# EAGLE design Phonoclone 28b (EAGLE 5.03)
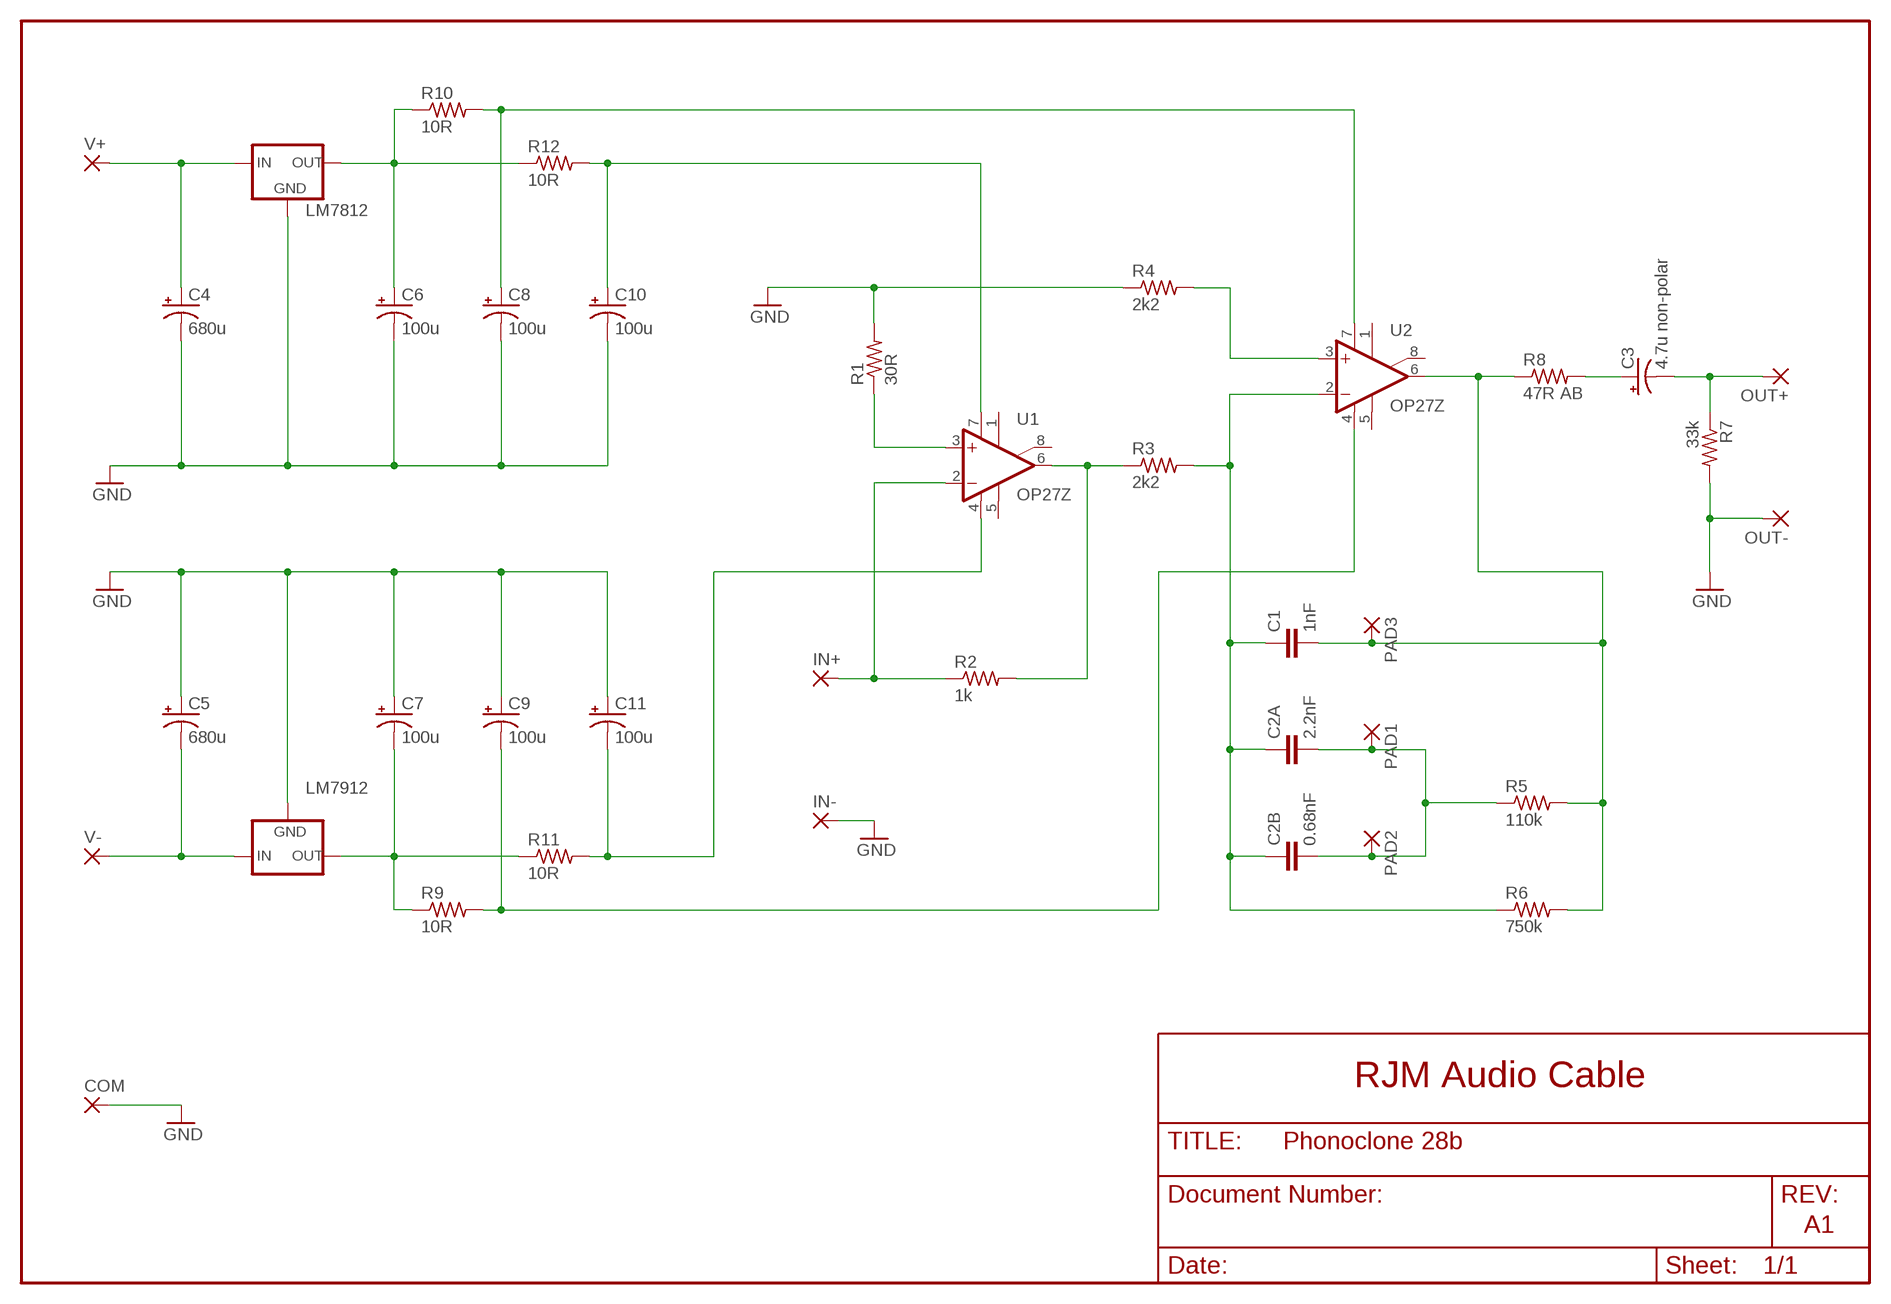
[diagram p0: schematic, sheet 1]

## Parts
C1  1nF  C-EU075-SS  [075-SS]
C2A  2.2nF  C-EU075-SS  [075-SS]
C2B  0.68nF  C-EU075-SS  [075-SS]
C3  4.7u non-polar  CPOL-USE2-5  [E2-5]
C4  680u  CPOL-USE5-10.5  [E5-10,5]
C5  680u  CPOL-USE5-10.5  [E5-10,5]
C6  100u  CPOL-USE2.5-6  [E2,5-6]
C7  100u  CPOL-USE2.5-6  [E2,5-6]
C8  100u  CPOL-USE2.5-6  [E2,5-6]
C9  100u  CPOL-USE2.5-6  [E2,5-6]
C10  100u  CPOL-USE2.5-6  [E2,5-6]
C11  100u  CPOL-USE2.5-6  [E2,5-6]
COM  3,17/1,3  [3,17/1,3]
IN+  2,15/1,0  [2,15/1,0]
IN-  2,15/1,0  [2,15/1,0]
LM7812  78XXS  [78XXS]
LM7912  79XXS  [79XXS]
OUT+  2,15/1,0  [2,15/1,0]
OUT-  2,15/1,0  [2,15/1,0]
PAD1  1,93/0,9  [1,93/0,9]
PAD2  1,93/0,9  [1,93/0,9]
PAD3  1,93/0,9  [1,93/0,9]
R1  30R  R-US_0207/10-SS  [0207/10-SS]
R2  1k  R-US_0207/10-SS  [0207/10-SS]
R3  2k2  R-US_0207/10-SS  [0207/10-SS]
R4  2k2  R-US_0207/10-SS  [0207/10-SS]
R5  110k  R-US_0207/10-SS  [0207/10-SS]
R6  750k  R-US_0207/10-SS  [0207/10-SS]
R7  33k  R-US_0207/10-SS  [0207/10-SS]
R8  47R AB  R-US_0207/10-SS  [0207/10-SS]
R9  10R  R-US_0207/10-SS  [0207/10-SS]
R10  10R  R-US_0207/10-SS  [0207/10-SS]
R11  10R  R-US_0207/10-SS  [0207/10-SS]
R12  10R  R-US_0207/10-SS  [0207/10-SS]
U1  OP27Z  [DIL08]
U2  OP27Z  [DIL08]
V+  3,17/1,3  [3,17/1,3]
V-  3,17/1,3  [3,17/1,3]

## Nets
GND: C4.- C5.+ C6.- C7.+ C8.- C9.+ C10.- C11.+ COM.1(P) IN-.1(P) LM7812.GND LM7912.GND OUT-.1(P) R1.2 R4.1 R7.2
IN: IN+.1(P) R2.1 U1.2(-IN)
N12_A: C9.- R9.2 U2.4(V-)
N12_B: C11.- R11.2 U1.4(V-)
N$1: R1.1 U1.3(+IN)
N$2: R4.2 U2.3(+IN)
N$4: C7.- LM7912.OUT R9.1 R11.1
N$5: C6.+ LM7812.OUT R10.1 R12.1
OUT: R2.2 R3.1 U1.6(OUT)
OUT1: C1.2 PAD3.1(P) R5.2 R6.2 R8.1 U2.6(OUT)
OUT2: C3.+ R8.2
OUT3: C3.- OUT+.1(P) R7.1
P12_A: C8.+ R10.2 U2.7(V+)
P12_B: C10.+ R12.2 U1.7(V+)
R1: C1.1 C2A.1 C2B.1 R3.2 R6.1 U2.2(-IN)
R2: C2A.2 C2B.2 PAD1.1(P) PAD2.1(P) R5.1
V+: C4.+ LM7812.IN V+.1(P)
V-: C5.- LM7912.IN V-.1(P)
Unconnected: U1.1(ON1) U1.5(OPT) U1.8(ON2) U2.1(ON1) U2.5(OPT) U2.8(ON2)

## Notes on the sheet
- RJM Audio Cable
- A1

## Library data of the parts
C1 C2A C2B = rcl:C-EU: CAPACITOR, European symbol
C3-C11 = rcl:CPOL-US: POLARIZED CAPACITOR, American symbol
COM V+ V- = wirepad:3,17/1,3: THROUGH-HOLE PAD
IN+ IN- OUT+ OUT- = wirepad:2,15/1,0: THROUGH-HOLE PAD
LM7812 = v-reg:78XXS: VOLTAGE REGULATOR
LM7912 = v-reg:79XXS: VOLTAGE REGULATOR
PAD1-PAD3 = wirepad:1,93/0,9: THROUGH HOLE PAD
R1-R12 = rcl:R-US_: RESISTOR, American symbol
U1 U2 = linear:OP27: OP AMP

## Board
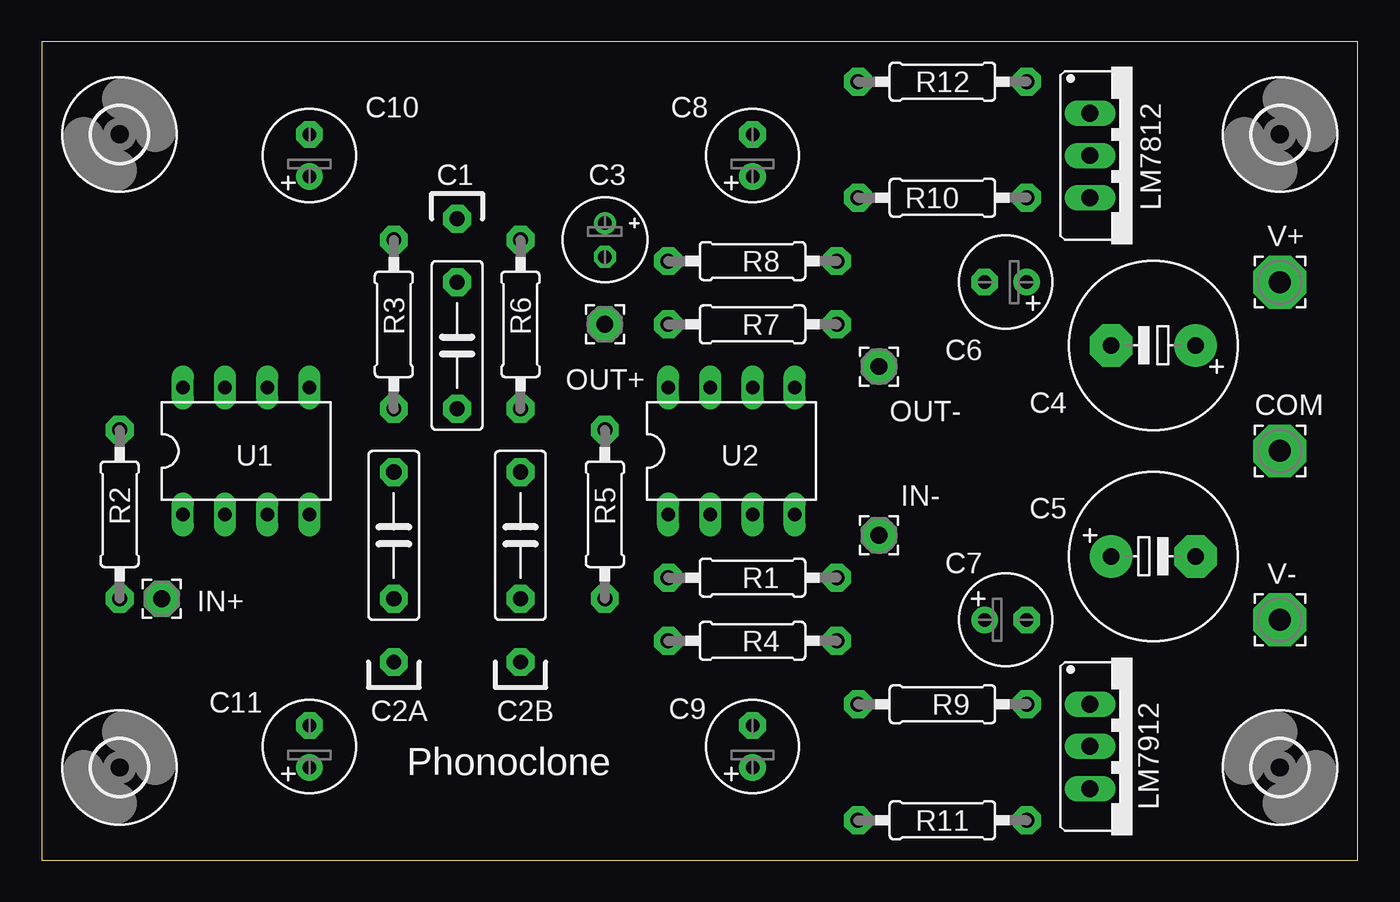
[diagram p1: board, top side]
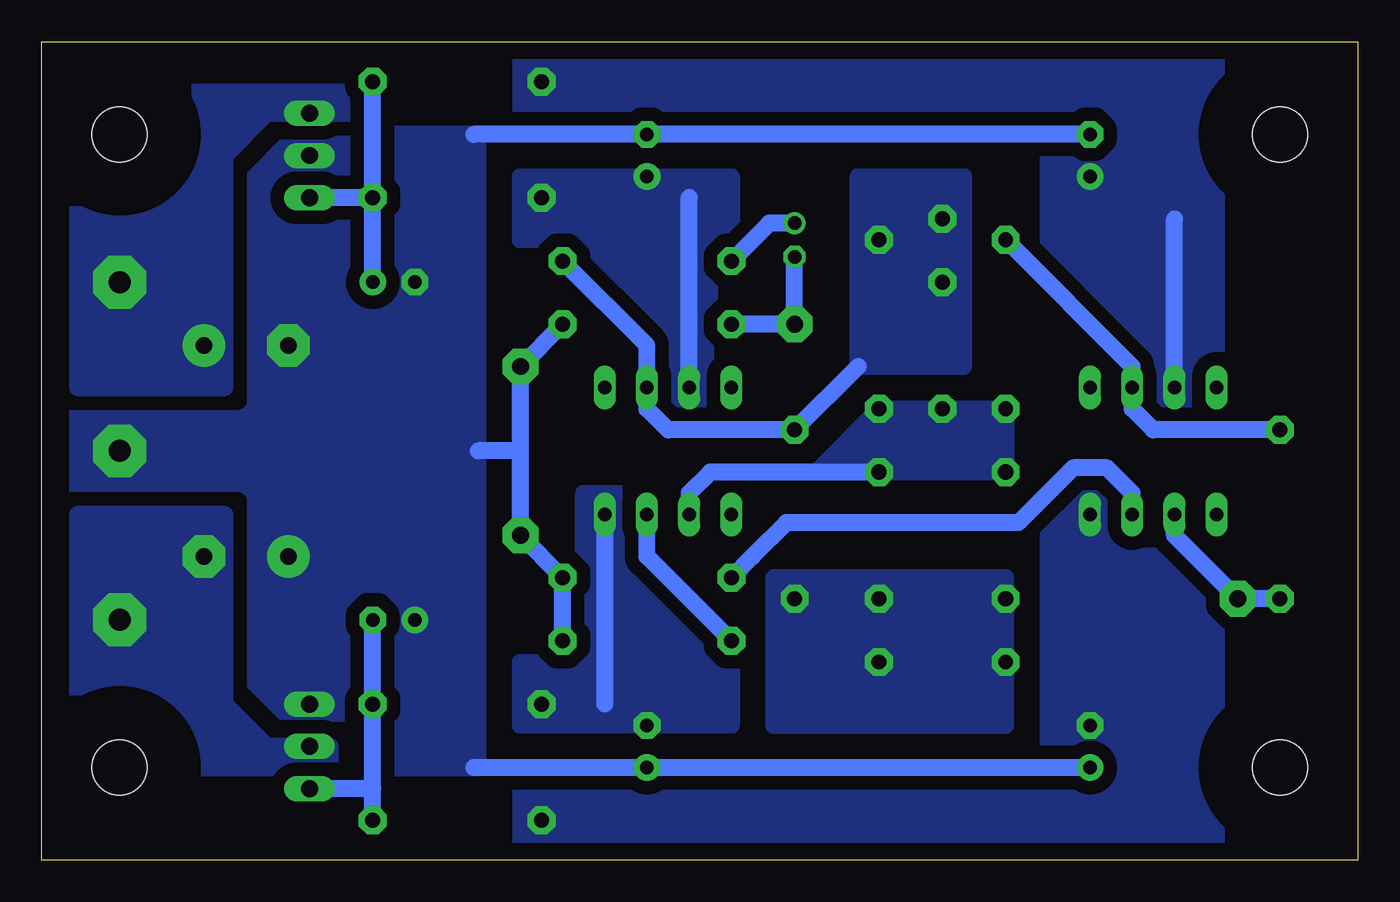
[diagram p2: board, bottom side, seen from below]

Size 79.25 x 49.28 mm. Coordinates in mm from the lower left corner, seen from the top.
Outline: 0,0 79.25,0 79.25,49.28 0,49.28 0,0
Copper layers (1*16): Top 0.035mm / dielectric 1.5mm / Bottom 0.035mm
Design rules "default": minimum track width 10mil, minimum drill 24mil, track to track 8mil, track to pad 8mil, pad to pad 8mil, via to via 8mil, smd to smd 8mil, copper to edge 40mil, drill to drill 8mil, minimum pad ring 10mil, minimum via ring 8mil, stop-mask expansion 4mil, vias tented up to drill 0mil, thermal gap 10mil

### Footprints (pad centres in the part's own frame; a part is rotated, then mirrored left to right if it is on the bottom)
075-SS = drill 0.914 pad 1.676 octagon: 1 -3.81,0; 2 3.81,0
E2-5 = drill 0.813 pad 1.27 round: + -1.016,0 | drill 0.813 pad 1.27 octagon: - 1.016,0
E5-10,5 = drill 1.016 pad 2.54 round: + -2.54,0 | drill 1.016 pad 2.54 octagon: - 2.54,0
E2,5-6 = drill 0.813 pad 1.6 round: + -1.27,0 | drill 0.813 pad 1.6 octagon: - 1.27,0
3,17/1,3 = drill 1.321 pad 3.175 octagon: 1 0,0
2,15/1,0 = drill 1.016 pad 2.159 octagon: 1 0,0
78XXS = drill 1.016 long: GND 0,-2.54; IN -2.54,-2.54; OUT 2.54,-2.54
79XXS = drill 1.016 long: GND -2.54,-2.54; IN 0,-2.54; OUT 2.54,-2.54
1,93/0,9 = drill 0.9 pad 1.676 octagon: 1 0,0
0207/10-SS = drill 0.9 pad 1.676 octagon: 1 -5.08,0; 2 5.08,0
DIL08 = drill 0.813 long: 1 -3.81,-3.81; 2 -1.27,-3.81; 3 1.27,-3.81; 4 3.81,-3.81; 5 3.81,3.81; 6 1.27,3.81; 7 -1.27,3.81; 8 -3.81,3.81
3,3 = hole 3.3: 0,0

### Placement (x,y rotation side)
C1  25.02,30.99 90 top
C2A  21.21,19.56 270 top
C2B  28.83,19.56 270 top
C3  33.91,37.34 270 top
C4  66.93,30.99 180 top
C5  66.93,18.29 0 top
C6  58.04,34.8 180 top
C7  58.04,14.48 0 top
C8  42.8,42.42 90 top
C9  42.8,6.86 90 top
C10  16.13,42.42 90 top
C11  16.13,6.86 90 top
COM  74.55,24.64 0 top
IN+  7.24,15.75 0 top
IN-  50.42,19.56 0 top
LM7812  65.66,42.42 270 top
LM7912  65.66,6.86 270 top
OUT+  33.91,32.26 0 top
OUT-  50.42,29.72 0 top
PAD1  21.21,11.94 0 top
PAD2  28.83,11.94 0 top
PAD3  25.02,38.61 0 top
R1  42.8,17.02 0 top
R2  4.7,20.83 90 top
R3  21.21,32.26 270 top
R4  42.8,13.21 180 top
R5  33.91,20.83 90 top
R6  28.83,32.26 90 top
R7  42.8,32.26 0 top
R8  42.8,36.07 180 top
R9  54.23,9.4 180 top
R10  54.23,39.88 180 top
R11  54.23,2.41 180 top
R12  54.23,46.86 180 top
U1  12.32,24.64 0 top
U2  41.53,24.64 0 top
U$1  [3,3]  4.7,43.69 0 top
U$2  [3,3]  74.55,43.69 0 top
U$3  [3,3]  74.55,5.59 90 top
U$4  [3,3]  4.7,5.59 0 top
V+  74.55,34.8 0 top
V-  74.55,14.48 0 top

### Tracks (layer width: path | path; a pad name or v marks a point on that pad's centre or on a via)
GND
  Bottom 1.016: R4.1 R1.2 IN-.1 50.42,24.64 | C10.- C8.- 53.21,43.69 | C11.+ C9.+ 53.21,5.59 | R7.2 OUT-.1 50.42,24.64 | 50.42,24.64 52.96,24.64
  pour Bottom (isolate 0.813, rank 4, no thermals): 77.09,43.69 77.09,5.59 52.96,5.59 52.96,43.69
IN
  Bottom 1.016: R2.1 IN+.1 11.05,19.56 U1.2
N12_A
  Bottom 1.016: 45.34,9.4 U2.4
  pour Bottom (isolate 0.813, rank 6, no thermals): 46.61,22.1 37.72,22.1 37.72,8.13 50.42,8.13 50.42,11.94 46.61,11.94
N12_B
  pour Bottom (isolate 0.813, rank 2, no thermals): 50.42,4.32 50.42,0.51 8.51,0.51 8.51,22.1 18.67,22.1 18.67,4.32
N$1
  Bottom 1.016: U1.3 13.59,22.1 15.11,23.62 17.14,23.62 20.45,20.32 34.42,20.32 36.45,18.29 R1.1
N$2
  Bottom 1.016: U2.3 42.8,18.29 R4.2
N$4
  Bottom 1.016: 59.31,4.32 R9.1 C7.- | R11.1 59.31,4.32 | 59.31,4.32 LM7912.OUT
N$5
  Bottom 1.016: R10.1 LM7812.OUT | C6.+ R10.1 | R10.1 R12.1
OUT
  Bottom 1.016: R3.1 13.59,29.72 U1.6 13.59,27.18 12.32,25.91 R2.2
OUT1
  Bottom 1.016: R8.1 42.8,30.99 U2.6 42.8,27.18 41.53,25.91 R5.2 30.1,29.72
  pour Bottom (isolate 0.813, rank 6, no thermals): 23.75,41.15 23.75,29.72 30.1,29.72 30.1,41.15
OUT2
  Bottom 1.016: C3.+ 35.43,38.35 R8.2
OUT3
  Bottom 1.016: OUT+.1 R7.1 OUT+.1 | OUT+.1 C3.-
P12_A
  Bottom 1.016: U2.7 40.26,39.88
  pour Bottom (isolate 0.813, rank 6, no thermals): 50.42,41.15 37.72,41.15 37.72,27.18 47.88,27.18 47.88,37.34 50.42,37.34
P12_B
  Bottom 1.016: U1.7 11.05,38.61
  pour Bottom (isolate 0.813, rank 2, no thermals): 18.67,27.18 8.51,27.18 8.51,48.77 50.42,48.77 50.42,44.96 18.67,44.96
R1
  Bottom 1.016: C2B.1 38.99,23.37 40.26,22.1 U2.2
  pour Bottom (isolate 0.813, rank 6, no thermals): 21.21,27.18 21.21,23.37 32.64,23.37 28.83,27.18
R2
  pour Bottom (isolate 0.813, rank 6, no thermals): 21.21,8.13 21.21,17.02 35.18,17.02 35.18,8.13
V+
  pour Bottom (isolate 0.813, no thermals): 60.58,46.23 77.09,46.23 77.09,28.45 68.2,28.45 68.2,42.42 65.66,44.96 60.58,44.96
V-
  pour Bottom (isolate 0.813, no thermals): 77.09,20.83 77.09,5.59 61.85,5.59 61.85,6.86 65.66,6.86 68.2,9.4 68.2,20.83

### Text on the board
tPlace: Phonoclone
